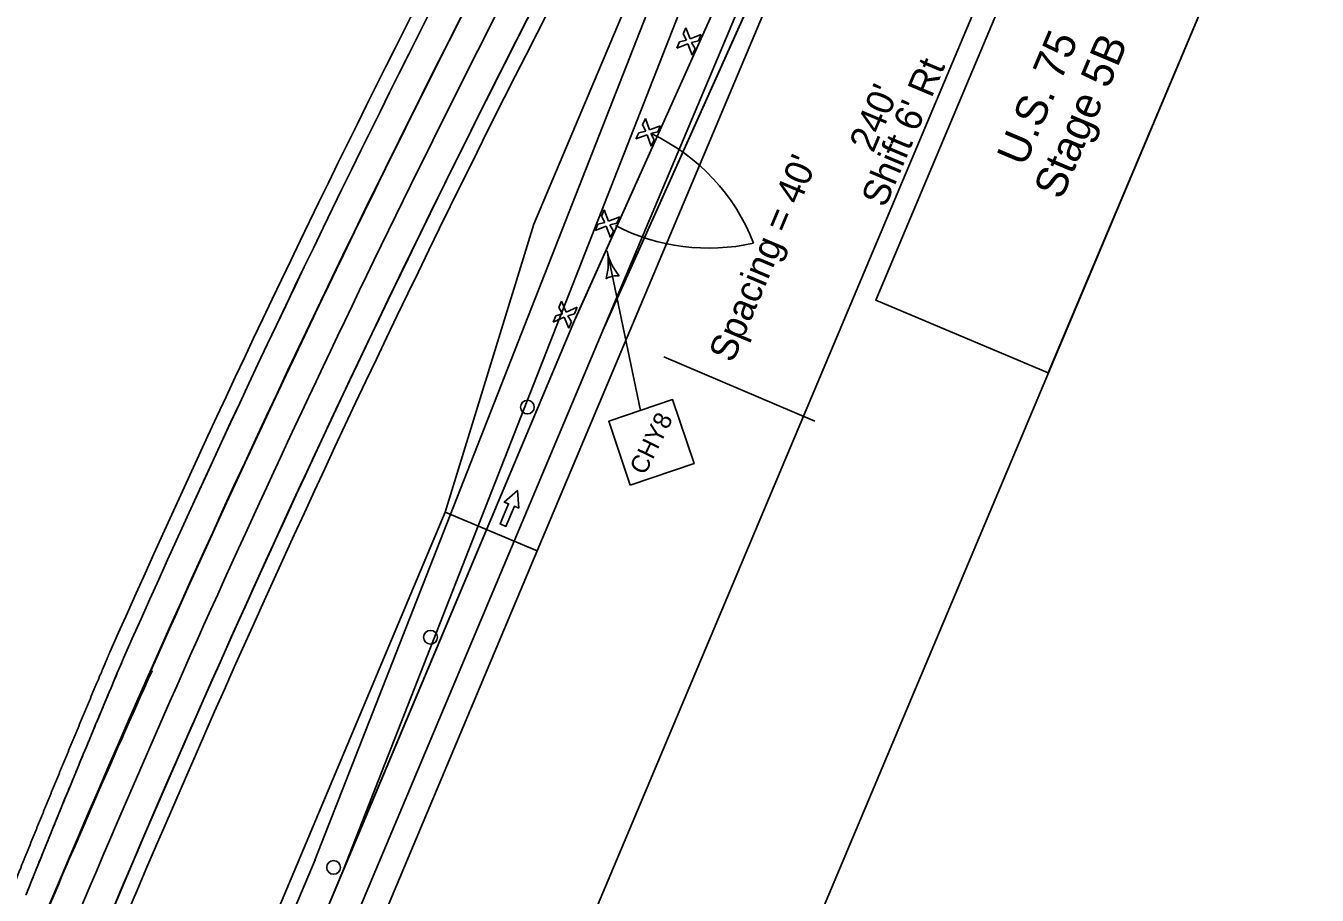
# Model space of a CAD drawing. Extents: x 14104283 to 14128447, y 8633203 to 8671666.
# Drawn here: x 14118644 to 14119161, y 8668018 to 8668366 of the extents above; entities that cross this region are included whole.
import ezdxf

# ---------------------------------------------------------------- set-up
doc = ezdxf.new("R2010")
doc.units = 0
for name, color, linetype in [('Cell', 7, 'Continuous'), ('dsnNonPlotable', 7, 'Continuous'), ('dsnPaintExistingBrokenLaneLineWhite', 7, 'Continuous'), ('dsnPaintExistingChannelizingLaneWhite', 7, 'Continuous'), ('dsnPaintExistingDottedLineWhite', 7, 'Continuous'), ('dsnPaintExistingEdgeLineLeftYellow', 7, 'Continuous'), ('dsnPaintExistingEdgeLineRightWhite', 7, 'Continuous'), ('dsnPaintPlaceChannelizingLaneYellow', 7, 'Continuous'), ('dsnPaintPlaceEdgeLineLeftYellow', 7, 'Continuous'), ('dsnPaintRemoveChannelizingWhite', 7, 'Continuous'), ('dsnPaintRemoveEdgeLineWhite', 7, 'Continuous'), ('dsnShadingPaved', 7, 'Continuous'), ('dsnStdLabel', 7, 'Continuous'), ('dsnStgShadingPrevPav', 7, 'Continuous'), ('dsnTapePlaceChannelizingLaneWhite', 7, 'Continuous'), ('dsnTapePlaceChannelizingLaneYellow', 7, 'Continuous'), ('dsnTapeRemoveChannelizingWhite', 7, 'Continuous'), ('dsnTapeRemoveChannelizingYellow', 7, 'Continuous'), ('dsnTextOverlapEven', 7, 'Continuous'), ('Level 2', 7, 'Continuous'), ('Level 5', 7, 'Continuous')]:
    doc.layers.add(name, color=color, linetype=linetype)

msp = doc.modelspace()

# ---------------------------------------------------------------- linework, layer by layer
at = {"layer": 'Cell'}
for p, q in [((14118907.88, 8668364.96), (14118906.78, 8668362.44)), ((14118906.78, 8668362.44), (14118908.14, 8668359.93)), ((14118909.62, 8668360.51), (14118907.88, 8668364.96)), ((14118914.07, 8668362.25), (14118909.62, 8668360.51)), ((14118912.96, 8668359.73), (14118914.07, 8668362.25)), ((14118905.38, 8668359.23), (14118904.27, 8668356.71)), ((14118904.27, 8668356.71), (14118908.72, 8668358.45)), ((14118908.14, 8668359.93), (14118905.38, 8668359.23)), ((14118908.72, 8668358.45), (14118910.46, 8668354.01)), ((14118910.2, 8668359.03), (14118912.96, 8668359.73)), ((14118911.56, 8668356.53), (14118910.2, 8668359.03)), ((14118910.46, 8668354.01), (14118911.56, 8668356.53)), ((14118891.67, 8668328.55), (14118890.51, 8668326.06)), ((14118890.51, 8668326.06), (14118891.81, 8668323.52)), ((14118893.31, 8668324.07), (14118891.67, 8668328.55)), ((14118897.79, 8668325.7), (14118893.31, 8668324.07)), ((14118896.63, 8668323.21), (14118897.79, 8668325.7)), ((14118889.03, 8668322.88), (14118887.87, 8668320.39)), ((14118887.87, 8668320.39), (14118892.36, 8668322.03)), ((14118891.81, 8668323.52), (14118889.03, 8668322.88)), ((14118892.36, 8668322.03), (14118893.99, 8668317.54)), ((14118893.85, 8668322.57), (14118896.63, 8668323.21)), ((14118895.15, 8668320.03), (14118893.85, 8668322.57)), ((14118893.99, 8668317.54), (14118895.15, 8668320.03)), ((14118875.24, 8668291.96), (14118874.12, 8668289.45)), ((14118874.12, 8668289.45), (14118875.46, 8668286.93)), ((14118876.94, 8668287.5), (14118875.24, 8668291.96)), ((14118881.4, 8668289.2), (14118876.94, 8668287.5)), ((14118880.28, 8668286.69), (14118881.4, 8668289.2)), ((14118872.69, 8668286.26), (14118871.57, 8668283.75)), ((14118871.57, 8668283.75), (14118876.03, 8668285.45)), ((14118875.46, 8668286.93), (14118872.69, 8668286.26)), ((14118876.03, 8668285.45), (14118877.73, 8668280.99)), ((14118877.51, 8668286.01), (14118880.28, 8668286.69)), ((14118878.85, 8668283.5), (14118877.51, 8668286.01)), ((14118877.73, 8668280.99), (14118878.85, 8668283.5)), ((14118858.05, 8668255.45), (14118857.04, 8668252.89)), ((14118857.04, 8668252.89), (14118858.5, 8668250.44)), ((14118859.96, 8668251.08), (14118858.05, 8668255.45)), ((14118864.33, 8668252.99), (14118859.96, 8668251.08)), ((14118863.33, 8668250.43), (14118864.33, 8668252.99)), ((14118855.77, 8668249.63), (14118854.76, 8668247.07)), ((14118854.76, 8668247.07), (14118859.14, 8668248.98)), ((14118858.5, 8668250.44), (14118855.77, 8668249.63)), ((14118859.14, 8668248.98), (14118861.05, 8668244.61)), ((14118860.6, 8668249.62), (14118863.33, 8668250.43)), ((14118862.05, 8668247.17), (14118860.6, 8668249.62)), ((14118861.05, 8668244.61), (14118862.05, 8668247.17))]:
    msp.add_line(p, q, dxfattribs=at)
for centre in [(14118844.44, 8668213.06), (14118805.61, 8668120.9), (14118766.79, 8668028.74)]:
    msp.add_circle(centre, 2.75, dxfattribs=at)
at = {"layer": 'dsnNonPlotable'}
msp.add_lwpolyline([(14118056.48, 8667161.91), (14118665.06, 8668606.45), (14119130.44, 8668410.38), (14118521.87, 8666965.84)], close=True, dxfattribs=at)
at = {"layer": 'dsnPaintExistingBrokenLaneLineWhite'}
msp.add_arc((14123732.96, 8665874.38), 5500, 152.69211, 157.1633, dxfattribs=at)
at = {"layer": 'dsnPaintExistingChannelizingLaneWhite'}
msp.add_line((14118766.99, 8668018.87), (14118770.49, 8668027.18), dxfattribs=at)
msp.add_line((14118766.99, 8668018.87), (14118770.49, 8668027.18), dxfattribs=at)
at = {"layer": 'dsnPaintExistingDottedLineWhite'}
msp.add_arc((14123732.96, 8665874.38), 5512, 152.23375, 154.51073, dxfattribs=at)
at = {"layer": 'dsnPaintExistingEdgeLineLeftYellow'}
msp.add_line((14115900.95, 8661243.95), (14118759.37, 8668031.7), dxfattribs=at)
msp.add_arc((14123732.96, 8665874.38), 5488, 152.69211, 157.1633, dxfattribs=at)
at = {"layer": 'dsnPaintExistingEdgeLineRightWhite'}
msp.add_line((14110924.38, 8649364.51), (14118874.68, 8668243.67), dxfattribs=at)
for centre, radius, start, end in [((14123732.96, 8665874.38), 5524, 150.3689, 156.09858), ((14123767.91, 8665959.11), 5522.39, 157.04925, 158.11426)]:
    msp.add_arc(centre, radius, start, end, dxfattribs=at)
at = {"layer": 'dsnPaintPlaceChannelizingLaneYellow'}
msp.add_line((14118537.63, 8667474.22), (14118770.49, 8668027.18), dxfattribs=at)
at = {"layer": 'dsnPaintPlaceEdgeLineLeftYellow'}
msp.add_line((14118770.49, 8668027.18), (14118863.73, 8668248.6), dxfattribs=at)
at = {"layer": 'dsnPaintRemoveChannelizingWhite'}
msp.add_line((14118766.99, 8668018.87), (14118537.63, 8667474.22), dxfattribs=at)
at = {"layer": 'dsnPaintRemoveEdgeLineWhite'}
msp.add_line((14118874.68, 8668243.67), (14118962.79, 8668452.92), dxfattribs=at)
at = {"layer": 'dsnShadingPaved'}
for p, q in [((14118982.24, 8668512.9), (14118863.67, 8668248.46)), ((14118874.67, 8668243.66), (14118993.21, 8668508.03)), ((14118863.73, 8668248.6), (14118766.99, 8668018.87)), ((14118249.84, 8666759.92), (14118874.67, 8668243.66)), ((14118693.64, 8668107.64), (14118694.07, 8668107.45)), ((14118766.99, 8668018.87), (14118537.63, 8667474.22))]:
    msp.add_line(p, q, dxfattribs=at)
for centre, radius, start, end in [((14123732.96, 8665874.38), 5512, 149.67774, 156.09858), ((14123732.96, 8665874.38), 5524, 150.3689, 153.23374), ((14123732.96, 8665874.38), 5512, 152.69211, 153.16925), ((14123732.96, 8665874.38), 5488, 152.69211, 157.1633), ((14123732.96, 8665874.38), 5512, 153.16925, 157.1633), ((14123732.96, 8665874.38), 5524, 153.23374, 156.09858), ((14123767.91, 8665959.11), 5522.39, 157.04925, 158.11426), ((14123265.63, 8666052.94), 5012, 155.80033, 157.1633)]:
    msp.add_arc(centre, radius, start, end, dxfattribs=at)
at = {"layer": 'dsnStdLabel'}
for p, q in [((14119048.19, 8668430.57), (14118955.01, 8668209.4)), ((14118876.36, 8668275.58), (14118889.78, 8668211.69)), ((14118899.13, 8668233.23), (14118959.61, 8668207.44)), ((14118955.01, 8668209.4), (14118798.76, 8667838.51))]:
    msp.add_line(p, q, dxfattribs=at)
msp.add_lwpolyline([(14118885.65, 8668181.79), (14118911.22, 8668190.45), (14118902.57, 8668216.02), (14118877, 8668207.37)], close=True, dxfattribs=at)
for centre, radius, start, end in [((14118860.14, 8668249.83), 80.21, 21.0762, 64.7827), ((14118917.04, 8668358.76), 82.08, 242.911, 282.6274), ((14118853.9, 8668270.86), 22.95, 343.7922, 11.8635), ((14118898.82, 8668280.3), 22.95, 191.8633, 219.9346), ((14118880.32, 8668256.75), 8.86, 84.1292, 119.5976)]:
    msp.add_arc(centre, radius, start, end, dxfattribs=at)
at = {"layer": 'dsnStgShadingPrevPav'}
for p, q in [((14118924.09, 8668469.22), (14118847.04, 8668286.26)), ((14118848.39, 8668155.49), (14118972.01, 8668449.04)), ((14118847.04, 8668286.26), (14118811.53, 8668171.01)), ((14115895.65, 8661246.83), (14118811.53, 8668171.01)), ((14118811.53, 8668171.01), (14118848.39, 8668155.49)), ((14118811.53, 8668171.01), (14118848.39, 8668155.49)), ((14118848.39, 8668155.49), (14115932.51, 8661231.3))]:
    msp.add_line(p, q, dxfattribs=at)
for centre, radius, start, end in [((14123732.96, 8665874.38), 5512, 146.42562, 157.1633), ((14123732.96, 8665874.38), 5488, 146.42119, 157.1633), ((14123732.96, 8665874.38), 5530, 150.3689, 156.09911), ((14123732.96, 8665874.38), 5524, 150.3689, 156.09858), ((14123732.96, 8665874.38), 5524, 150.3689, 156.09858), ((14123732.59, 8665873.82), 5512, 150.36196, 157.1633), ((14123732.96, 8665874.38), 5482, 150.67101, 157.1633), ((14123732.96, 8665874.38), 5488, 151.14296, 157.1633)]:
    msp.add_arc(centre, radius, start, end, dxfattribs=at)
for points, degree in [([(14118677.15, 8668114.84), (14118676.77, 8668113.95), (14118675.45, 8668110.85), (14118673.07, 8668105.18), (14118671.18, 8668100.7), (14118669.16, 8668095.89), (14118667.19, 8668091.17), (14118665.21, 8668086.42), (14118663.23, 8668081.68), (14118661.26, 8668076.94), (14118659.29, 8668072.19), (14118657.33, 8668067.44), (14118655.38, 8668062.69), (14118653.42, 8668057.94), (14118651.47, 8668053.18), (14118649.53, 8668048.43), (14118647.59, 8668043.66), (14118645.66, 8668038.92), (14118643.7, 8668034.09), (14118641.88, 8668029.58), (14118639.58, 8668023.88), (14118638.32, 8668020.76), (14118637.96, 8668019.85)], 2), ([(14118643.53, 8668017.62), (14118644.16, 8668019.2), (14118645.44, 8668022.38), (14118647.36, 8668027.14), (14118649.28, 8668031.89), (14118651.21, 8668036.65), (14118653.15, 8668041.4), (14118655.08, 8668046.16), (14118657.03, 8668050.91), (14118658.97, 8668055.66), (14118660.92, 8668060.4), (14118662.88, 8668065.15), (14118664.84, 8668069.89), (14118666.8, 8668074.63), (14118668.77, 8668079.37), (14118670.74, 8668084.11), (14118672.72, 8668088.85), (14118674.7, 8668093.58), (14118676.69, 8668098.32), (14118678.68, 8668103.05), (14118680.67, 8668107.78), (14118682.01, 8668110.93), (14118682.67, 8668112.51)], 3), ([(14118643.53, 8668017.62), (14118644.16, 8668019.2), (14118645.44, 8668022.38), (14118647.36, 8668027.14), (14118649.28, 8668031.89), (14118651.21, 8668036.65), (14118653.15, 8668041.4), (14118655.08, 8668046.16), (14118657.03, 8668050.91), (14118658.97, 8668055.66), (14118660.92, 8668060.4), (14118662.88, 8668065.15), (14118664.84, 8668069.89), (14118666.8, 8668074.63), (14118668.77, 8668079.37), (14118670.74, 8668084.11), (14118672.72, 8668088.85), (14118674.7, 8668093.58), (14118676.69, 8668098.32), (14118678.68, 8668103.05), (14118680.67, 8668107.78), (14118682.01, 8668110.93), (14118682.67, 8668112.51)], 3)]:
    msp.add_open_spline(points, degree=degree, dxfattribs=at)
at = {"layer": 'dsnTapePlaceChannelizingLaneWhite'}
msp.add_lwpolyline([(14118874.68, 8668243.67), (14118933.94, 8668375.85), (14118972.98, 8668462.66)], dxfattribs=at)
at = {"layer": 'dsnTapePlaceChannelizingLaneYellow'}
msp.add_lwpolyline([(14118863.73, 8668248.6), (14118922.96, 8668380.68), (14118962.33, 8668467.19)], dxfattribs=at)
at = {"layer": 'dsnTapeRemoveChannelizingWhite'}
msp.add_line((14118770.49, 8668027.18), (14118945.77, 8668474.25), dxfattribs=at)
at = {"layer": 'dsnTapeRemoveChannelizingYellow'}
msp.add_line((14118759.32, 8668031.57), (14118934.66, 8668478.8), dxfattribs=at)
at = {"layer": 'dsnTextOverlapEven'}
for points in [[(14119130.44, 8668410.38), (14119053.07, 8668226.74), (14118983.96, 8668255.86), (14119061.32, 8668439.5)], [(14118983.96, 8668255.86), (14119061.32, 8668439.5), (14119130.44, 8668410.38), (14119053.07, 8668226.74)]]:
    msp.add_lwpolyline(points, close=True, dxfattribs=at)
at = {"layer": 'Level 2'}
msp.add_lwpolyline([(14118833.5, 8668166.24), (14118835.8, 8668165.27), (14118839.2, 8668173.34), (14118840.93, 8668172.61), (14118840.47, 8668179.58), (14118835.17, 8668175.03), (14118836.89, 8668174.31)], close=True, dxfattribs=at)
at = {"layer": 'Level 5'}
msp.add_lwpolyline([(14118836.89, 8668174.31), (14118835.17, 8668175.03), (14118840.47, 8668179.58), (14118840.93, 8668172.61), (14118839.2, 8668173.34), (14118835.8, 8668165.27), (14118833.5, 8668166.24), (14118836.89, 8668174.31)], dxfattribs=at)

# ---------------------------------------------------------------- texts
at = {"layer": 'dsnStdLabel'}
for s, height, rotation, p in [("Shift 6' Rt", 10.8, 67.1547, (14118987.74, 8668292.49)), ("240'", 10.8, 67.1547, (14118982.94, 8668314.49)), ("Spacing = 40'", 10.8, 67.1547, (14118926.69, 8668230.38)), ('CHY8', 7.2, 63.6912, (14118891.49, 8668185.48))]:
    msp.add_text(s, height=height, rotation=rotation, dxfattribs=at).set_placement(p)
at = {"layer": 'dsnTextOverlapEven'}
for s, p in [('U.S. 75', (14119043.6, 8668308.9)), ('Stage 5B', (14119058.36, 8668295.63))]:
    msp.add_text(s, height=12.5, rotation=67.1547, dxfattribs=at).set_placement(p)

doc.saveas('drawing.dxf')
